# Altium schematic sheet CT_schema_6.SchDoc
size 305 x 256 mm
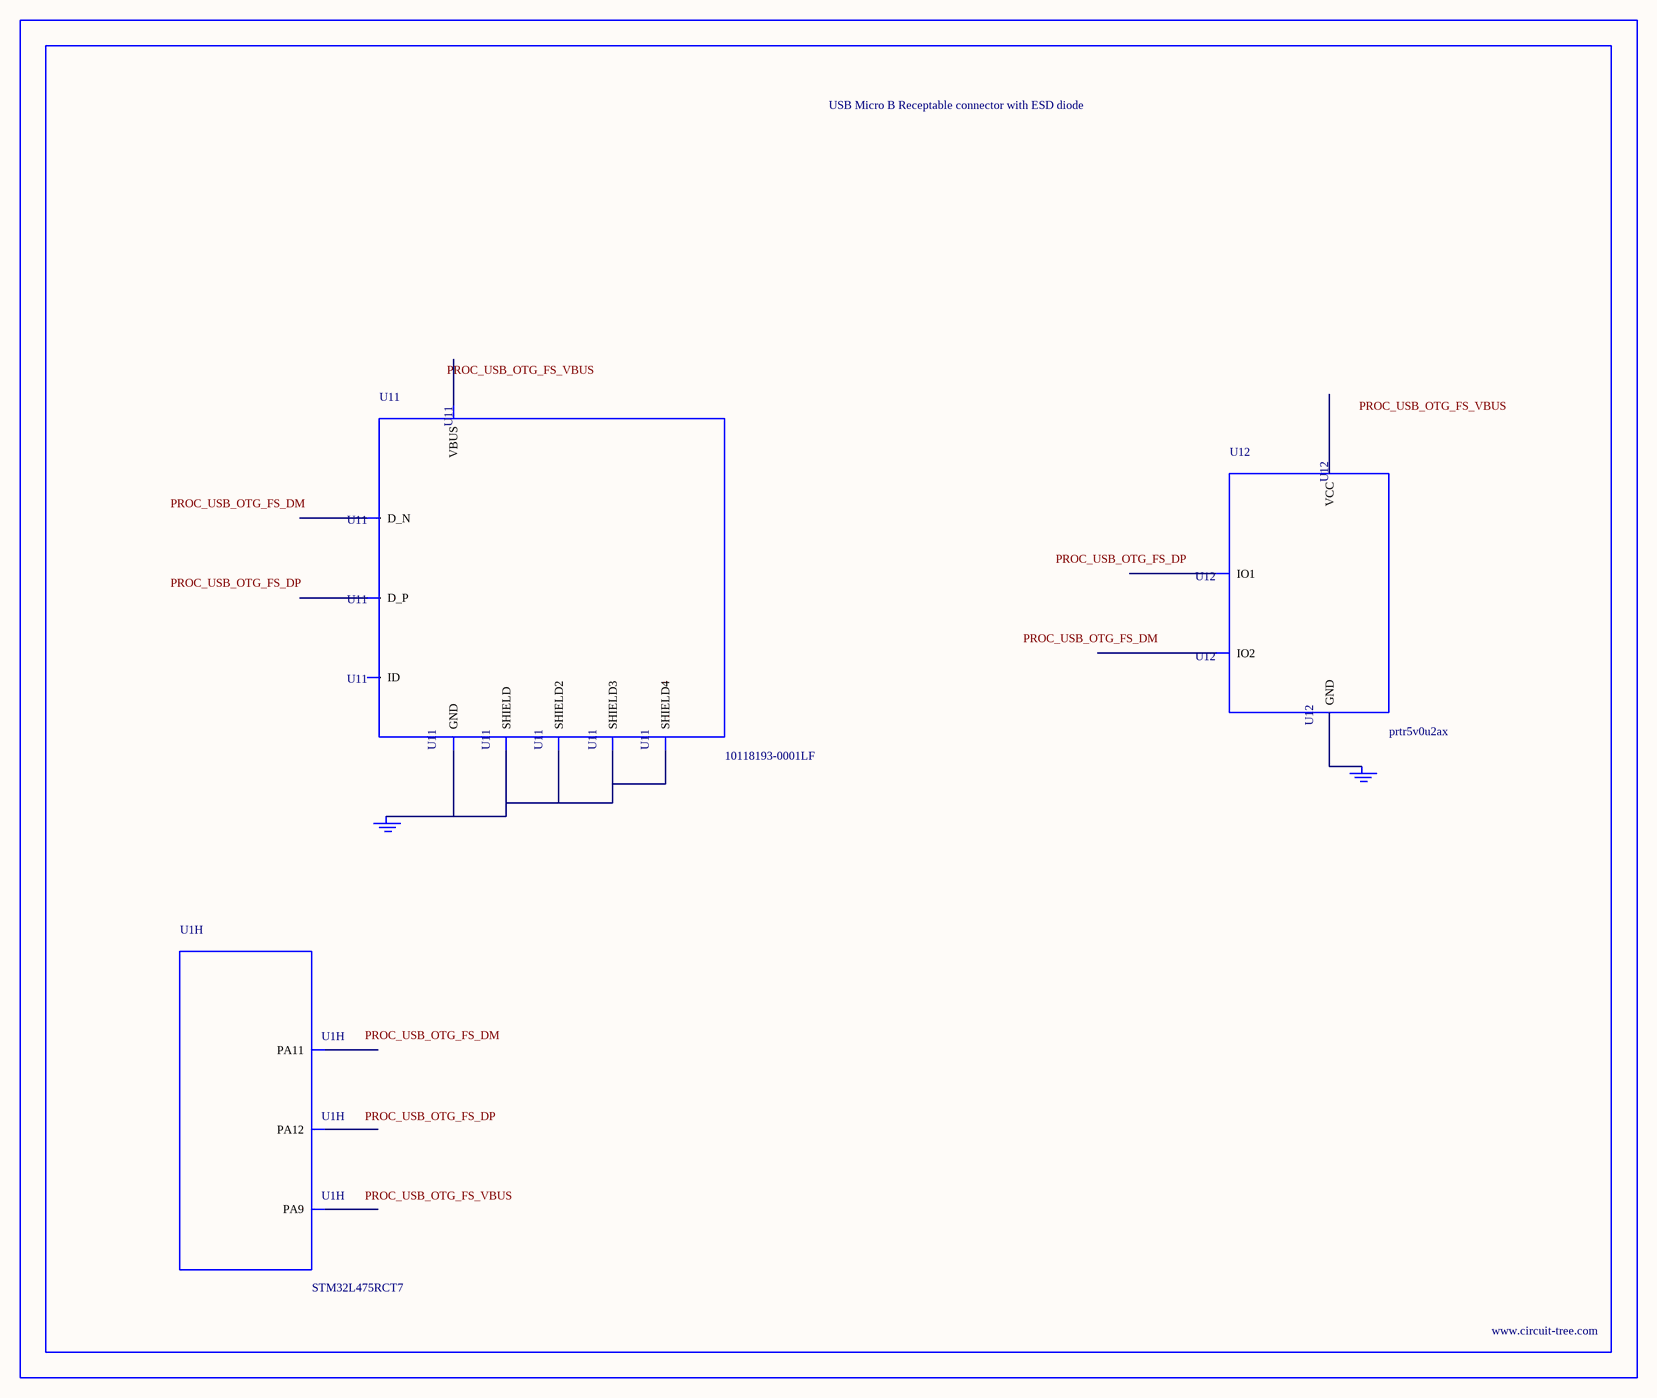
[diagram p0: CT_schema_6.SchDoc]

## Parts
BORDER5  (no value)
GND_INSTANCE_5_0  (no value)
GND_INSTANCE_5_1  (no value)
U1  STM32L475RCT7  [LQFP64]  (part H of 8)
U11  10118193-0001LF  [FCI_10118193-0001LF]
U12  prtr5v0u2ax  [SOT143B]

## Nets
NetGND_INSTANCE_5_0_0: GND_INSTANCE_5_0.0(GND) U11.5(GND) U11.6(SHIELD) U11.7(SHIELD2) U11.8(SHIELD3) U11.9(SHIELD4)
NetGND_INSTANCE_5_1_0: GND_INSTANCE_5_1.0(GND) U12.1(GND)

Not connected (* = marked no-connect by the designer): U1 42(PA9) 44(PA11) 45(PA12); U11 1(VBUS) 2(D_N) 3(D_P) 4(ID); U12 2(IO1) 3(IO2) 4(VCC)

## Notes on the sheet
- Labels drawn without touching a wire or pin: PROC_USB_OTG_FS_DM, PROC_USB_OTG_FS_DP, PROC_USB_OTG_FS_VBUS

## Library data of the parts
BORDER5 = BORDER_PAGE5
GND_INSTANCE_5_0 GND_INSTANCE_5_1 = GND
